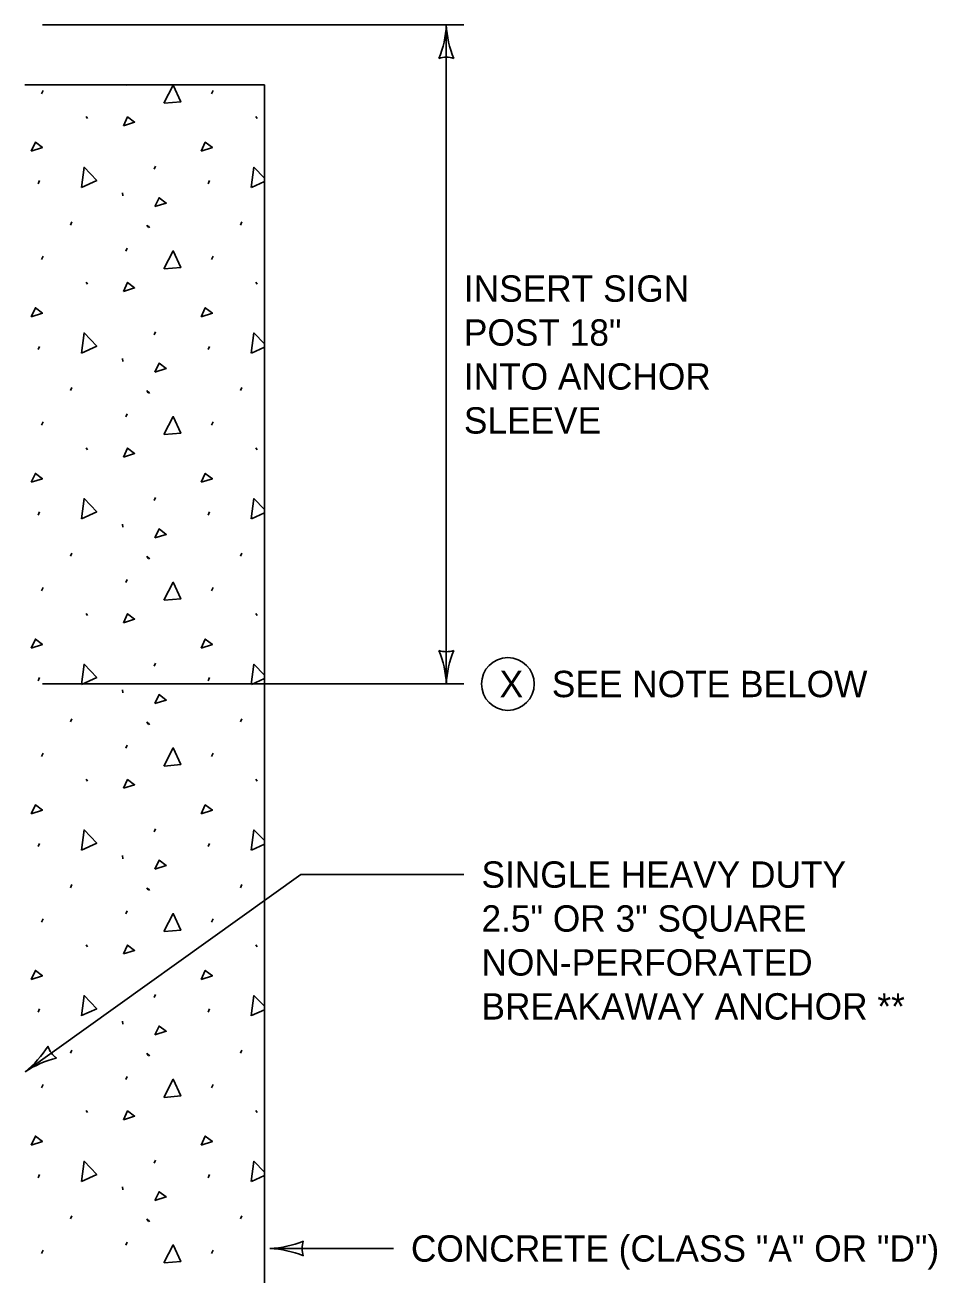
# Model space of a CAD drawing. Extents: x 49940 to 50043, y 49986 to 50011.
# Drawn here: x 49964.546 to 49966.62, y 49992.591 to 49995.433 of the extents above; entities that cross this region are included whole.
import ezdxf

# ---------------------------------------------------------------- set-up
doc = ezdxf.new("R2010")
doc.units = 0
for name, color, linetype in [('Level 1', 7, 'Continuous'), ('Level 2', 7, 'Continuous'), ('Level 3', 7, 'Continuous')]:
    doc.layers.add(name, color=color, linetype=linetype)

msp = doc.modelspace()

# ---------------------------------------------------------------- linework, layer by layer
at = {"layer": 'Level 1'}
for p, q in [((49965.0906, 49995.2967), (49964.5454, 49995.2967)), ((49964.5836, 49995.2767), (49964.5869, 49995.2839)), ((49964.7749, 49995.2952), (49964.7756, 49995.2967)), ((49964.9702, 49995.2767), (49964.9734, 49995.2839)), ((49965.0906, 49992.5705), (49965.0906, 49995.2967)), ((49964.6846, 49995.225), (49964.6877, 49995.2202)), ((49965.0711, 49995.225), (49965.0742, 49995.2202)), ((49964.8395, 49995.1049), (49964.8427, 49995.112)), ((49964.5756, 49995.0716), (49964.5788, 49995.079)), ((49964.9622, 49995.0716), (49964.9654, 49995.079)), ((49964.7675, 49995.0514), (49964.7682, 49995.0442)), ((49964.649, 49994.978), (49964.6523, 49994.9853)), ((49964.8226, 49994.978), (49964.8257, 49994.9733)), ((49964.8257, 49994.9762), (49964.829, 49994.9713)), ((49965.0357, 49994.978), (49965.0387, 49994.9853)), ((49964.7749, 49994.9183), (49964.7782, 49994.9255)), ((49964.5836, 49994.8997), (49964.5869, 49994.9069)), ((49964.9702, 49994.8997), (49964.9734, 49994.9069)), ((49964.6846, 49994.8481), (49964.6877, 49994.8432)), ((49965.0711, 49994.8481), (49965.0742, 49994.8432)), ((49964.8395, 49994.7278), (49964.8427, 49994.735)), ((49964.5756, 49994.6947), (49964.5788, 49994.7019)), ((49964.9622, 49994.6947), (49964.9654, 49994.7019)), ((49964.7675, 49994.6744), (49964.7682, 49994.6672)), ((49964.649, 49994.6011), (49964.6523, 49994.6083)), ((49964.8226, 49994.6011), (49964.8257, 49994.5963)), ((49964.8257, 49994.5993), (49964.829, 49994.5945)), ((49965.0357, 49994.6011), (49965.0387, 49994.6083)), ((49964.7749, 49994.5413), (49964.7782, 49994.5486)), ((49964.5836, 49994.5228), (49964.5869, 49994.53)), ((49964.9702, 49994.5228), (49964.9734, 49994.53)), ((49964.6846, 49994.4712), (49964.6877, 49994.4663)), ((49965.0711, 49994.4712), (49965.0742, 49994.4663)), ((49964.8395, 49994.3508), (49964.8427, 49994.3581)), ((49964.5756, 49994.3178), (49964.5788, 49994.325)), ((49964.9622, 49994.3178), (49964.9654, 49994.325)), ((49964.7675, 49994.2975), (49964.7682, 49994.2903)), ((49964.649, 49994.2241), (49964.6523, 49994.2314)), ((49965.0357, 49994.2241), (49965.0387, 49994.2314)), ((49964.8226, 49994.2241), (49964.8257, 49994.2193)), ((49964.8257, 49994.2223), (49964.829, 49994.2175)), ((49964.7749, 49994.1643), (49964.7782, 49994.1716)), ((49964.5836, 49994.1457), (49964.5869, 49994.1532)), ((49964.9702, 49994.1457), (49964.9734, 49994.1532)), ((49964.6846, 49994.0941), (49964.6877, 49994.0893)), ((49965.0711, 49994.0941), (49965.0742, 49994.0893)), ((49964.8395, 49993.9739), (49964.8427, 49993.9812)), ((49964.5756, 49993.9408), (49964.5788, 49993.9481)), ((49964.9622, 49993.9408), (49964.9654, 49993.9481)), ((49964.7675, 49993.9205), (49964.7682, 49993.9133)), ((49964.649, 49993.8472), (49964.6523, 49993.8545)), ((49964.8226, 49993.8472), (49964.8257, 49993.8423)), ((49964.8257, 49993.8453), (49964.829, 49993.8404)), ((49965.0357, 49993.8472), (49965.0387, 49993.8545)), ((49964.5836, 49993.7688), (49964.5869, 49993.776)), ((49964.7749, 49993.7874), (49964.7782, 49993.7947)), ((49964.9702, 49993.7688), (49964.9734, 49993.776)), ((49964.6846, 49993.7171), (49964.6877, 49993.7124)), ((49965.0711, 49993.7171), (49965.0742, 49993.7124)), ((49964.8395, 49993.5969), (49964.8427, 49993.6041)), ((49964.5756, 49993.5639), (49964.5788, 49993.571)), ((49964.9622, 49993.5639), (49964.9654, 49993.571)), ((49964.7675, 49993.5435), (49964.7682, 49993.5361)), ((49964.649, 49993.4701), (49964.6523, 49993.4775)), ((49964.8226, 49993.4701), (49964.8257, 49993.4653)), ((49964.8257, 49993.4683), (49964.829, 49993.4635)), ((49965.0357, 49993.4701), (49965.0387, 49993.4775)), ((49964.7749, 49993.4104), (49964.7782, 49993.4176)), ((49964.5836, 49993.3919), (49964.5869, 49993.3991)), ((49964.9702, 49993.3919), (49964.9734, 49993.3991)), ((49964.6846, 49993.3401), (49964.6877, 49993.3354)), ((49965.0711, 49993.3401), (49965.0742, 49993.3354)), ((49964.8395, 49993.22), (49964.8427, 49993.2272)), ((49964.5756, 49993.1869), (49964.5788, 49993.1941)), ((49964.9622, 49993.1869), (49964.9654, 49993.1941)), ((49964.7675, 49993.1666), (49964.7682, 49993.1592)), ((49964.649, 49993.0933), (49964.6523, 49993.1005)), ((49964.8226, 49993.0933), (49964.8257, 49993.0884)), ((49964.8257, 49993.0914), (49964.829, 49993.0867)), ((49965.0357, 49993.0933), (49965.0387, 49993.1005)), ((49964.7749, 49993.0334), (49964.7782, 49993.0407)), ((49964.5836, 49993.0149), (49964.5869, 49993.0221)), ((49964.9702, 49993.0149), (49964.9734, 49993.0221)), ((49964.6846, 49992.9632), (49964.6877, 49992.9584)), ((49965.0711, 49992.9632), (49965.0742, 49992.9584)), ((49964.8395, 49992.843), (49964.8427, 49992.8503)), ((49964.5756, 49992.8099), (49964.5788, 49992.8171)), ((49964.9622, 49992.8099), (49964.9654, 49992.8171)), ((49964.7675, 49992.7896), (49964.7682, 49992.7824)), ((49964.649, 49992.7163), (49964.6523, 49992.7235)), ((49965.0357, 49992.7163), (49965.0387, 49992.7235)), ((49964.8226, 49992.7163), (49964.8257, 49992.7114)), ((49964.8257, 49992.7144), (49964.829, 49992.7096)), ((49964.7749, 49992.6565), (49964.7782, 49992.6637)), ((49964.5836, 49992.6379), (49964.5869, 49992.6451)), ((49964.9702, 49992.6379), (49964.9734, 49992.6451))]:
    msp.add_line(p, q, dxfattribs=at)
for points in [[(49964.8614, 49995.255), (49964.883, 49995.2961), (49964.9, 49995.2582), (49964.8621, 49995.255)], [(49964.7694, 49995.2039), (49964.7789, 49995.2242), (49964.7951, 49995.2121), (49964.7694, 49995.2039)], [(49964.5596, 49995.1463), (49964.5693, 49995.1665), (49964.5854, 49995.1544), (49964.5596, 49995.1463)], [(49964.9461, 49995.1463), (49964.9558, 49995.1665), (49964.972, 49995.1544), (49964.9461, 49995.1463)], [(49964.6739, 49995.0634), (49964.6802, 49995.1095), (49964.7091, 49995.0796), (49964.6745, 49995.0636)], [(49965.0604, 49995.0634), (49965.0666, 49995.1095), (49965.0906, 49995.085)], [(49965.0906, 49995.0772), (49965.0611, 49995.0636)], [(49964.8411, 49995.02), (49964.8508, 49995.0402), (49964.867, 49995.0281), (49964.8411, 49995.02)], [(49964.8614, 49994.878), (49964.883, 49994.9191), (49964.9, 49994.8812), (49964.8621, 49994.878)], [(49964.7694, 49994.8271), (49964.7789, 49994.8473), (49964.7951, 49994.835), (49964.7694, 49994.8271)], [(49964.5596, 49994.7694), (49964.5693, 49994.7897), (49964.5854, 49994.7774), (49964.5596, 49994.7694)], [(49964.9461, 49994.7694), (49964.9558, 49994.7897), (49964.972, 49994.7774), (49964.9461, 49994.7694)], [(49964.6739, 49994.6863), (49964.6802, 49994.7324), (49964.7091, 49994.7027), (49964.6745, 49994.6866)], [(49965.0604, 49994.6863), (49965.0666, 49994.7324), (49965.0906, 49994.7079)], [(49965.0906, 49994.7003), (49965.0611, 49994.6866)], [(49964.8411, 49994.643), (49964.8508, 49994.6633), (49964.867, 49994.6513), (49964.8411, 49994.643)], [(49964.8614, 49994.501), (49964.883, 49994.5421), (49964.9, 49994.5042), (49964.8621, 49994.501)], [(49964.7694, 49994.4501), (49964.7789, 49994.4703), (49964.7951, 49994.4581), (49964.7694, 49994.4501)], [(49964.5596, 49994.3925), (49964.5693, 49994.4126), (49964.5854, 49994.4005), (49964.5596, 49994.3925)], [(49964.9461, 49994.3925), (49964.9558, 49994.4126), (49964.972, 49994.4005), (49964.9461, 49994.3925)], [(49964.6739, 49994.3094), (49964.6802, 49994.3556), (49964.7091, 49994.3256), (49964.6745, 49994.3097)], [(49965.0604, 49994.3094), (49965.0666, 49994.3556), (49965.0906, 49994.331)], [(49965.0906, 49994.3233), (49965.0611, 49994.3097)], [(49964.8411, 49994.2661), (49964.8508, 49994.2863), (49964.867, 49994.2741), (49964.8411, 49994.2661)], [(49964.8614, 49994.124), (49964.883, 49994.1651), (49964.9, 49994.1271), (49964.8621, 49994.124)], [(49964.7694, 49994.0731), (49964.7789, 49994.0933), (49964.7951, 49994.0813), (49964.7694, 49994.0731)], [(49964.5596, 49994.0154), (49964.5693, 49994.0357), (49964.5854, 49994.0236), (49964.5596, 49994.0154)], [(49964.9461, 49994.0154), (49964.9558, 49994.0357), (49964.972, 49994.0236), (49964.9461, 49994.0154)], [(49964.6739, 49993.9325), (49964.6802, 49993.9787), (49964.7091, 49993.9486), (49964.6745, 49993.9327)], [(49965.0604, 49993.9325), (49965.0666, 49993.9787), (49965.0906, 49993.954)], [(49965.0906, 49993.9463), (49965.0611, 49993.9327)], [(49964.8411, 49993.889), (49964.8508, 49993.9094), (49964.867, 49993.8971), (49964.8411, 49993.889)], [(49964.8614, 49993.7469), (49964.883, 49993.7881), (49964.9, 49993.7503), (49964.8621, 49993.7469)], [(49964.7694, 49993.6962), (49964.7789, 49993.7162), (49964.7951, 49993.7043), (49964.7694, 49993.6962)], [(49964.5596, 49993.6385), (49964.5693, 49993.6586), (49964.5854, 49993.6465), (49964.5596, 49993.6385)], [(49964.9461, 49993.6385), (49964.9558, 49993.6586), (49964.972, 49993.6465), (49964.9461, 49993.6385)], [(49964.6739, 49993.5554), (49964.6802, 49993.6016), (49964.7091, 49993.5717), (49964.6745, 49993.5557)], [(49965.0604, 49993.5554), (49965.0666, 49993.6016), (49965.0906, 49993.5771)], [(49965.0906, 49993.5694), (49965.0611, 49993.5557)], [(49964.8411, 49993.5122), (49964.8508, 49993.5324), (49964.867, 49993.5202), (49964.8411, 49993.5122)], [(49964.8614, 49993.3701), (49964.883, 49993.4111), (49964.9, 49993.3733), (49964.8621, 49993.3701)], [(49964.7694, 49993.3193), (49964.7789, 49993.3393), (49964.7951, 49993.3273), (49964.7694, 49993.3193)], [(49964.5596, 49993.2615), (49964.5693, 49993.2817), (49964.5854, 49993.2697), (49964.5596, 49993.2615)], [(49964.9461, 49993.2615), (49964.9558, 49993.2817), (49964.972, 49993.2697), (49964.9461, 49993.2615)], [(49964.6739, 49993.1784), (49964.6802, 49993.2246), (49964.7091, 49993.1947), (49964.6745, 49993.1789)], [(49965.0604, 49993.1784), (49965.0666, 49993.2246), (49965.0906, 49993.2001)], [(49965.0906, 49993.1923), (49965.0611, 49993.1789)], [(49964.8411, 49993.1353), (49964.8508, 49993.1553), (49964.867, 49993.1433), (49964.8411, 49993.1353)], [(49964.8614, 49992.993), (49964.883, 49993.0342), (49964.9, 49992.9962), (49964.8621, 49992.993)], [(49964.7694, 49992.9421), (49964.7789, 49992.9623), (49964.7951, 49992.9503), (49964.7694, 49992.9421)], [(49964.5596, 49992.8845), (49964.5693, 49992.9047), (49964.5854, 49992.8927), (49964.5596, 49992.8845)], [(49964.9461, 49992.8845), (49964.9558, 49992.9047), (49964.972, 49992.8927), (49964.9461, 49992.8845)], [(49964.6739, 49992.8015), (49964.6802, 49992.8476), (49964.7091, 49992.8178), (49964.6745, 49992.8018)], [(49965.0604, 49992.8015), (49965.0666, 49992.8476), (49965.0906, 49992.8231)], [(49965.0906, 49992.8153), (49965.0611, 49992.8018)], [(49964.8411, 49992.7583), (49964.8508, 49992.7783), (49964.867, 49992.7663), (49964.8411, 49992.7583)], [(49964.8614, 49992.6162), (49964.883, 49992.6573), (49964.9, 49992.6193), (49964.8621, 49992.6162)]]:
    msp.add_lwpolyline(points, dxfattribs=at)
at = {"layer": 'Level 2'}
msp.add_circle((49965.6441, 49993.9336), 0.06, dxfattribs=at)
at = {"layer": 'Level 3'}
for p, q in [((49964.5854, 49995.4332), (49965.5441, 49995.4332)), ((49965.5041, 49995.4332), (49965.5041, 49993.9336)), ((49964.5854, 49993.9336), (49965.5441, 49993.9336)), ((49964.5459, 49993.0514), (49965.1731, 49993.5)), ((49965.1731, 49993.5), (49965.5441, 49993.5)), ((49965.1028, 49992.649), (49965.3836, 49992.649))]:
    msp.add_line(p, q, dxfattribs=at)
for centre, radius, start, end in [((49965.282, 49995.4424), 0.2223, 337.456, 357.6395), ((49965.7368, 49995.4447), 0.233, 182.8273, 202.0772), ((49965.5041, 49995.305), 0.0548, 72.1388, 107.8612), ((49965.5041, 49994.0618), 0.0548, 252.1388, 287.8612), ((49965.2714, 49993.9221), 0.233, 2.8273, 22.0772), ((49965.7263, 49993.9245), 0.2223, 157.456, 177.6395), ((49964.4012, 49993.234), 0.233, 308.404, 327.6539), ((49964.6502, 49993.126), 0.0548, 197.7155, 233.4379), ((49964.6677, 49992.8654), 0.2223, 103.0327, 123.2162), ((49965.0913, 49992.8817), 0.233, 272.8273, 292.0772), ((49965.231, 49992.649), 0.0548, 162.1388, 197.8612), ((49965.0937, 49992.4269), 0.2223, 67.456, 87.6395)]:
    msp.add_arc(centre, radius, start, end, dxfattribs=at)

# ---------------------------------------------------------------- texts
at = {"layer": 'Level 2'}
for s, p in [('INSERT SIGN', (49965.5441, 49994.8034)), ('POST 18"', (49965.5441, 49994.7034)), ('INTO ANCHOR', (49965.5441, 49994.6034)), ('SLEEVE', (49965.5441, 49994.5034)), ('X', (49965.6253, 49993.9036)), ('SEE NOTE BELOW', (49965.7441, 49993.9036)), ('SINGLE HEAVY DUTY', (49965.5841, 49993.47)), ('2.5" OR 3" SQUARE', (49965.5841, 49993.37)), ('NON-PERFORATED', (49965.5841, 49993.27)), ('BREAKAWAY ANCHOR **', (49965.5841, 49993.17)), ('CONCRETE (CLASS "A" OR "D")', (49965.4236, 49992.619))]:
    msp.add_text(s, height=0.06, dxfattribs=at).set_placement(p)

doc.saveas('drawing.dxf')
